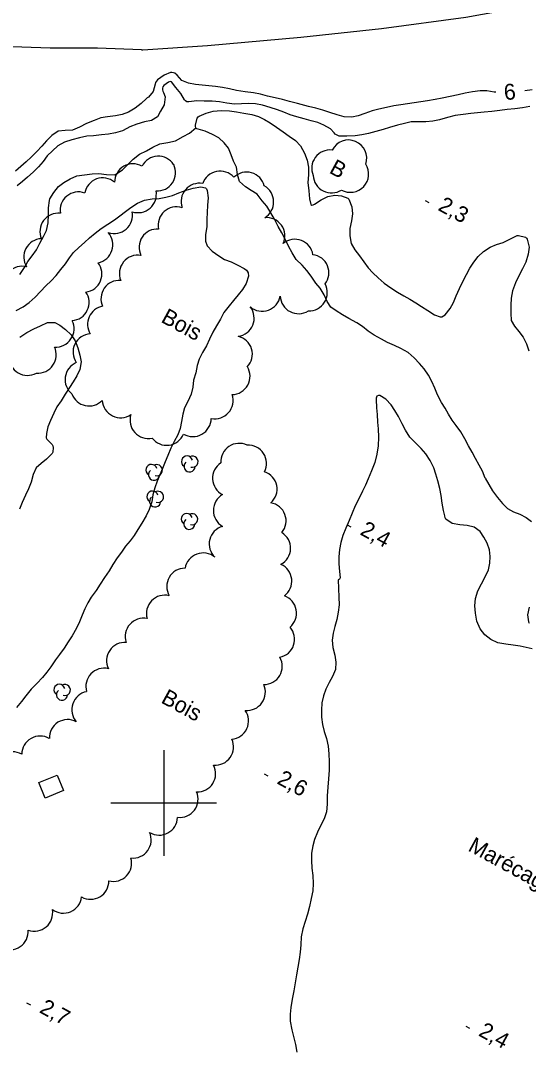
# Model space of a CAD drawing. Extents: x 219136 to 222520, y 5421589 to 5424530.
# Drawn here: x 220572.9 to 220669, y 5422953.1 to 5423147.8 of the extents above; entities that cross this region are included whole.
import ezdxf

# ---------------------------------------------------------------- set-up
doc = ezdxf.new("R2010")
doc.units = 0
for name, color, linetype in [('Level 2', 7, 'Continuous'), ('Level 21', 7, 'Continuous'), ('Level 3', 7, 'Continuous'), ('Level 31', 7, 'Continuous'), ('Level 4', 7, 'Continuous'), ('Level 44', 7, 'Continuous'), ('Level 61', 7, 'Continuous'), ('Level 7', 7, 'Continuous')]:
    doc.layers.add(name, color=color, linetype=linetype)

msp = doc.modelspace()

# ---------------------------------------------------------------- linework, layer by layer
at = {"layer": 'Level 2'}
for points in [[(220630.06, 5423130.89), (220628.77, 5423131.28), (220627.39, 5423131.58), (220625.32, 5423132.19), (220623.8, 5423132.58), (220622.44, 5423132.91), (220621.05, 5423133.24), (220619.65, 5423133.56), (220618.28, 5423133.91), (220616.99, 5423134.19), (220615.4, 5423134.37), (220613.76, 5423134.62), (220612.47, 5423134.97), (220611.11, 5423135.22), (220609.8, 5423135.36), (220608.53, 5423135.49), (220607.27, 5423135.64), (220606.01, 5423135.76), (220604.7, 5423136.01), (220603.44, 5423136.49), (220602.54, 5423137.54), (220602.1, 5423137.92), (220601.85, 5423138), (220601.54, 5423138.03), (220601.26, 5423138.01), (220600.08, 5423137.53), (220598.84, 5423136.64), (220598.46, 5423136.12), (220598.36, 5423135.82), (220598, 5423134.44), (220597.09, 5423133.35), (220596.84, 5423133.22), (220596.72, 5423133.13)], [(220604.13, 5423132.65), (220603.95, 5423132.87), (220603.23, 5423134.09), (220602.32, 5423135.21), (220601.46, 5423136.24), (220601.2, 5423136.33), (220600.93, 5423136.22), (220599.99, 5423135.57), (220599.85, 5423135.34), (220599.78, 5423135.07), (220599.77, 5423134.78), (220599.83, 5423134.51), (220599.97, 5423134.23), (220600.29, 5423133.41), (220600.06, 5423131.91), (220599.42, 5423130.72), (220598.84, 5423129.66), (220597.69, 5423128.97), (220596.36, 5423128.68), (220594.9, 5423128.25), (220593.56, 5423127.75), (220592.36, 5423127.09), (220592.22, 5423127.02)], [(220662.81, 5423134.33), (220662.47, 5423134.34), (220661.13, 5423134.54), (220659.83, 5423134.59), (220658.39, 5423134.4), (220656.99, 5423134.11), (220655.67, 5423133.81), (220654.15, 5423133.47), (220652.66, 5423133.16), (220651.31, 5423132.9), (220649.89, 5423132.69), (220648.65, 5423132.5), (220647.39, 5423132.31), (220646.1, 5423132.12), (220644.81, 5423131.94), (220643.53, 5423131.73), (220642.11, 5423131.43), (220640.67, 5423131.12), (220639.44, 5423130.81), (220638.04, 5423130.31), (220636.8, 5423129.86), (220635.55, 5423129.58), (220634.12, 5423129.66), (220632.81, 5423130.03), (220631.43, 5423130.5), (220630.06, 5423130.89)], [(220669.65, 5423134.78), (220668.32, 5423134.57)], [(220596.72, 5423133.13), (220595.75, 5423132.16), (220594.63, 5423131.31), (220593.34, 5423130.55), (220592.13, 5423130.08), (220590.86, 5423129.87), (220589.38, 5423129.68), (220588.08, 5423129.46), (220586.85, 5423128.97), (220585.41, 5423128.39), (220584.09, 5423127.7), (220582.72, 5423127.15), (220581.35, 5423127.07), (220580.01, 5423126.92), (220578.87, 5423126.12), (220577.86, 5423125.11), (220576.92, 5423124.13), (220575.99, 5423123.11), (220574.93, 5423122.05), (220573.96, 5423121.13), (220572.97, 5423120.28), (220571.98, 5423119.38)], [(220669.25, 5423131.59), (220667.88, 5423131.37), (220666.42, 5423131.14), (220664.96, 5423131.02), (220663.55, 5423130.87), (220662.02, 5423130.66), (220660.62, 5423130.54), (220659.36, 5423130.43), (220658.05, 5423130.27), (220656.61, 5423130.08), (220655.14, 5423129.9), (220653.67, 5423129.51), (220652.16, 5423129.1), (220650.9, 5423128.81), (220649.56, 5423128.69), (220648.22, 5423128.71), (220646.77, 5423128.7), (220645.53, 5423128.41), (220644.19, 5423128.05), (220642.71, 5423127.63), (220641.52, 5423127.24), (220640.1, 5423126.87), (220638.73, 5423126.51), (220637.47, 5423126.23), (220636.22, 5423126.09), (220634.64, 5423125.98), (220633.17, 5423126.02), (220632.4, 5423126.39), (220632.23, 5423126.6), (220631.56, 5423127.39), (220630.3, 5423128.09), (220629.13, 5423128.59), (220627.89, 5423128.93), (220626.59, 5423129.25), (220625.17, 5423129.64), (220623.94, 5423130.05), (220622.7, 5423130.53), (220621.5, 5423130.99), (220620.16, 5423131.43), (220618.65, 5423131.83), (220617.37, 5423132.09), (220616.1, 5423132.18), (220614.72, 5423132.11), (220613.36, 5423132.06), (220611.96, 5423132.26), (220610.55, 5423132.52), (220609.17, 5423132.6), (220607.64, 5423132.61), (220606.24, 5423132.65), (220604.73, 5423132.47), (220604.37, 5423132.51), (220604.13, 5423132.65)], [(220592.22, 5423127.02), (220590.88, 5423126.63), (220589.53, 5423126.37), (220588.22, 5423126.24), (220586.74, 5423126.09), (220585.48, 5423125.97), (220584.08, 5423125.69), (220582.6, 5423125.32), (220581.21, 5423124.85), (220580, 5423124.2), (220578.96, 5423123.26), (220577.97, 5423122.27), (220577.22, 5423121.24), (220576.34, 5423120.22), (220575.29, 5423119.18), (220574.25, 5423118.23), (220573.28, 5423117.41), (220572.26, 5423116.61)], [(220575.72, 5423095.58), (220576.67, 5423096.63), (220577.71, 5423097.73), (220578.71, 5423098.67), (220579.66, 5423099.66), (220580.57, 5423100.78), (220581.42, 5423101.9), (220582.18, 5423103), (220582.96, 5423103.99), (220583.94, 5423104.98), (220585, 5423105.89), (220585.99, 5423106.78), (220587.01, 5423107.68), (220588.15, 5423108.53), (220589.43, 5423109.38), (220590.69, 5423110.16), (220591.7, 5423110.95), (220592.75, 5423111.75), (220593.78, 5423112.54), (220595.02, 5423113.34), (220596.35, 5423113.91), (220597.83, 5423114.15), (220599.15, 5423114.24), (220600.41, 5423114.45), (220601.67, 5423114.8), (220602.85, 5423115.3), (220604.23, 5423115.82), (220605.56, 5423116.19), (220607.03, 5423116.42), (220607.87, 5423116.24), (220608.07, 5423116.03), (220608.21, 5423115.75), (220608.39, 5423114.36), (220608.29, 5423112.98), (220608.24, 5423111.59), (220608.18, 5423110.33), (220608.13, 5423108.87), (220607.93, 5423107.43), (220607.88, 5423106.16), (220608.2, 5423105.25), (220609.18, 5423104.28), (220610.42, 5423103.4), (220611.5, 5423102.72), (220612.75, 5423102.23), (220614.01, 5423101.63), (220615.22, 5423101.02), (220615.66, 5423100.7), (220615.81, 5423100.48), (220615.94, 5423100.2), (220616.04, 5423099.56), (220615.61, 5423098.15), (220614.87, 5423097.03), (220614.06, 5423096), (220613.19, 5423094.95), (220612.39, 5423093.91), (220611.39, 5423092.66), (220610.72, 5423091.45), (220609.95, 5423090.19), (220609.28, 5423088.96), (220608.68, 5423087.63), (220608.1, 5423086.41), (220607.36, 5423085.1), (220606.73, 5423083.88), (220606.35, 5423082.66), (220606.05, 5423081.26)], [(220572.11, 5423093.03), (220573.41, 5423093.75), (220574.58, 5423094.56), (220575.72, 5423095.58)], [(220572.76, 5423088.04), (220574.09, 5423088.88), (220575.43, 5423089.6), (220576.68, 5423090.19), (220578.02, 5423090.77), (220579.41, 5423090.77), (220580.38, 5423090.29), (220581.43, 5423089.47), (220582.48, 5423088.49), (220583.27, 5423087.3), (220583.73, 5423086.03), (220584.11, 5423084.59), (220584.39, 5423083.34), (220584.12, 5423081.92), (220583.55, 5423080.73), (220582.87, 5423079.58), (220582.15, 5423078.53), (220581.38, 5423077.27), (220580.6, 5423075.99), (220579.81, 5423074.83), (220579.23, 5423073.63), (220578.6, 5423072.29), (220578.11, 5423071.08), (220577.82, 5423069.81), (220577.75, 5423069), (220577.89, 5423068.77), (220578.89, 5423067.76), (220579.01, 5423067.49), (220579.07, 5423067.2), (220579.04, 5423066.29), (220578.91, 5423066.02), (220577.85, 5423064.99), (220576.81, 5423064.15), (220575.87, 5423063.3), (220575.3, 5423062.09), (220574.94, 5423060.64), (220574.41, 5423059.39), (220573.84, 5423058.18), (220573.26, 5423056.79), (220572.73, 5423055.52)], [(220606.05, 5423081.26), (220605.64, 5423079.91), (220605.51, 5423078.58), (220605.21, 5423077.23), (220604.55, 5423075.87), (220603.96, 5423074.67), (220603.61, 5423073.47), (220603.36, 5423072.06), (220603.11, 5423070.76), (220602.68, 5423069.55), (220601.95, 5423068.32), (220601.36, 5423067.02), (220600.8, 5423065.66), (220600.27, 5423064.45), (220599.77, 5423063.23), (220599.26, 5423062.03), (220598.74, 5423060.79), (220598.29, 5423059.57), (220597.95, 5423058.21), (220597.77, 5423056.93), (220597.26, 5423055.44), (220596.65, 5423054.23), (220595.86, 5423052.87), (220595.11, 5423051.68), (220594.38, 5423050.57), (220593.63, 5423049.54), (220592.8, 5423048.5), (220592.04, 5423047.42), (220591.17, 5423046.29), (220590.38, 5423045.04), (220589.71, 5423043.89), (220588.82, 5423042.59), (220588, 5423041.34), (220587.2, 5423040.13), (220586.3, 5423038.91), (220585.65, 5423037.81), (220585.08, 5423036.66), (220584.6, 5423035.46), (220584.08, 5423034.21), (220583.53, 5423033.03), (220582.7, 5423031.58), (220581.93, 5423030.43), (220581.15, 5423029.24), (220580.3, 5423028.05), (220579.53, 5423027.02), (220578.66, 5423025.72), (220577.92, 5423024.7), (220577.07, 5423023.71), (220575.99, 5423022.59), (220574.95, 5423021.5), (220573.94, 5423020.26), (220573.09, 5423019.2), (220572.13, 5423018.05)]]:
    msp.add_lwpolyline(points, dxfattribs=at)
at = {"layer": 'Level 21'}
for points in [[(220595.78, 5423142.32), (220596.07, 5423142.34), (220608.3, 5423143.12), (220625.95, 5423144.72), (220641.18, 5423146.34), (220657.15, 5423148.52), (220677.44, 5423152.18)], [(220595.78, 5423142.32), (220587.48, 5423142.64), (220578.53, 5423142.66), (220562.37, 5423143.22), (220541.52, 5423144.77), (220523.65, 5423145.87), (220511.93, 5423146.79), (220506.04, 5423146.14), (220502.22, 5423144.49), (220498.38, 5423141.58), (220495.91, 5423137.1), (220483.71, 5423103.12), (220471.88, 5423067.02), (220455.93, 5423018.9), (220442.13, 5422979.2), (220434.81, 5422959.19)]]:
    msp.add_lwpolyline(points, dxfattribs=at)
at = {"layer": 'Level 3'}
for p, q in [((220649.45, 5423113.85), (220650.15, 5423113.47)), ((220634.71, 5423052.55), (220635.41, 5423052.17)), ((220619.01, 5423005.49), (220619.71, 5423005.11)), ((220574.08, 5422962.23), (220574.78, 5422961.85)), ((220657.12, 5422957.85), (220657.82, 5422957.47))]:
    msp.add_line(p, q, dxfattribs=at)
at = {"layer": 'Level 31'}
msp.add_lwpolyline([(220579.88, 5423005.25), (220581.06, 5423002.34), (220577.56, 5423000.93), (220576.39, 5423003.84)], close=True, dxfattribs=at)
at = {"layer": 'Level 4'}
for points in [[(220606.08, 5423127.57), (220606, 5423127.82), (220606.01, 5423128.08), (220606.3, 5423129.41), (220606.49, 5423129.63), (220606.71, 5423129.76), (220608.05, 5423130.33), (220609.37, 5423130.75), (220610.89, 5423130.85), (220612.44, 5423130.77), (220613.76, 5423130.59), (220615.15, 5423130.35), (220616.64, 5423130.09), (220617.9, 5423129.7), (220619.03, 5423129.13), (220620.15, 5423128.54), (220621.33, 5423127.73), (220622.59, 5423126.82), (220623.74, 5423125.98), (220624.9, 5423125.16), (220625.87, 5423124.18), (220626.64, 5423122.76), (220627.15, 5423121.49), (220627.4, 5423120.15), (220627.4, 5423118.72), (220627.26, 5423117.27), (220627.45, 5423115.69), (220627.58, 5423114.19), (220627.8, 5423113.11), (220628.03, 5423112.96), (220628.29, 5423113), (220628.54, 5423113.14), (220629.76, 5423113.94), (220631.01, 5423114.59), (220632.33, 5423114.84), (220633.62, 5423114.75), (220634.8, 5423114.27), (220635, 5423114.07), (220635.57, 5423112.65), (220635.71, 5423111.31), (220635.48, 5423110), (220635.19, 5423108.58), (220635.18, 5423107.15), (220635.46, 5423105.74), (220636.15, 5423104.52), (220637, 5423103.41), (220637.87, 5423102.24), (220638.65, 5423101.12), (220639.52, 5423100.2), (220640.58, 5423099.26), (220641.72, 5423098.25), (220642.94, 5423097.31), (220644.18, 5423096.53), (220645.4, 5423095.82), (220646.57, 5423095.21), (220647.68, 5423094.52), (220648.75, 5423093.81), (220649.94, 5423093.03), (220651.21, 5423092.21), (220652.28, 5423091.84), (220652.62, 5423091.87), (220652.94, 5423092.03), (220653.24, 5423092.23), (220654.15, 5423093.41)], [(220572.81, 5423099.84), (220573.66, 5423101.19), (220574.33, 5423102.34), (220575.1, 5423103.41), (220575.93, 5423104.53), (220576.59, 5423105.78), (220577.28, 5423107.03), (220577.82, 5423108.18), (220578.12, 5423109.64), (220578.2, 5423111.2), (220578.24, 5423112.49), (220578.38, 5423113.87), (220578.49, 5423114.13), (220579.2, 5423115.34), (220580.11, 5423116.49), (220581.1, 5423117.27), (220582.33, 5423117.96), (220583.57, 5423118.52), (220585.03, 5423118.72), (220586.49, 5423118.89), (220587.75, 5423118.97), (220589.17, 5423118.75), (220590.69, 5423118.71), (220590.94, 5423118.81), (220592.19, 5423119.65), (220593.25, 5423120.7), (220594.23, 5423121.68), (220595.44, 5423122.59), (220596.72, 5423123.25), (220597.95, 5423123.91), (220599.25, 5423124.55), (220600.78, 5423124.81), (220602.22, 5423125.13), (220603.68, 5423125.91), (220604.86, 5423126.56), (220606.06, 5423127.55), (220606.08, 5423127.57)], [(220660.82, 5423061.37), (220660.29, 5423062.68), (220659.68, 5423063.82), (220658.99, 5423065.06), (220658.32, 5423066.28), (220657.65, 5423067.51), (220656.94, 5423068.81), (220656.18, 5423070.14), (220655.32, 5423071.32), (220654.52, 5423072.35), (220653.84, 5423073.45), (220653.21, 5423074.59), (220652.52, 5423075.68), (220651.78, 5423077.12), (220651.24, 5423078.39), (220650.69, 5423079.61), (220650.09, 5423080.82), (220649.25, 5423082.05), (220648.38, 5423083.07), (220647.35, 5423084.13), (220646.22, 5423085.13), (220644.86, 5423085.9), (220643.62, 5423086.47), (220642.33, 5423087.03), (220641.16, 5423087.62), (220639.82, 5423088.38), (220638.67, 5423089.18), (220637.6, 5423090.01), (220636.54, 5423090.75), (220635, 5423091.52), (220633.82, 5423092.26), (220632.62, 5423092.97), (220631.6, 5423093.69), (220630.93, 5423094.78), (220630.32, 5423096.01), (220629.56, 5423097.26), (220628.77, 5423098.25), (220627.91, 5423099.52), (220627.08, 5423100.64), (220626.2, 5423101.61), (220625.06, 5423102.69), (220624.27, 5423103.97), (220623.57, 5423105.23), (220622.98, 5423106.53), (220622.35, 5423107.74), (220621.67, 5423108.96), (220620.94, 5423110.29), (220620.27, 5423111.53), (220619.51, 5423112.77), (220618.64, 5423113.81), (220617.7, 5423115.03), (220616.51, 5423115.75), (220615.44, 5423116.43), (220614.36, 5423117.45), (220613.97, 5423118.77), (220613.79, 5423120.14), (220613.22, 5423121.28), (220612.75, 5423122.5), (220612.23, 5423123.75), (220611.44, 5423124.76), (220610.41, 5423125.71), (220609.23, 5423126.32), (220607.85, 5423126.93), (220606.51, 5423127.3), (220606.26, 5423127.38), (220606.08, 5423127.57)], [(220654.15, 5423093.41), (220654.77, 5423094.6), (220655.33, 5423095.82), (220655.93, 5423097.23), (220656.58, 5423098.55), (220657.28, 5423099.87), (220657.9, 5423101.04), (220658.64, 5423102.2), (220659.44, 5423103.24), (220660.47, 5423104.19), (220661.74, 5423105), (220662.92, 5423105.53), (220664.22, 5423105.93), (220665.59, 5423106.62), (220666.83, 5423107.2), (220667.09, 5423107.23), (220668.4, 5423106.92), (220668.6, 5423106.74), (220668.76, 5423106.52), (220669.1, 5423105.03), (220668.91, 5423103.68), (220668.48, 5423102.22), (220667.88, 5423100.95), (220667.17, 5423099.59), (220666.55, 5423098.28), (220665.98, 5423096.78), (220665.71, 5423095.39), (220665.64, 5423094.06), (220665.63, 5423092.57), (220665.68, 5423091.19), (220666.31, 5423090.07), (220667.14, 5423089.07), (220667.97, 5423088.03), (220668.62, 5423086.73), (220669.06, 5423085.42)], [(220660.82, 5423061.37), (220661.48, 5423060.15), (220662.19, 5423058.96), (220663.12, 5423057.71), (220664.07, 5423056.56), (220665, 5423055.62), (220666.16, 5423055.03), (220667.33, 5423054.58), (220668.53, 5423053.97), (220669.52, 5423053.19)], [(220669.11, 5423036.97), (220668.8, 5423035.58), (220668.96, 5423034.25), (220669.11, 5423034)]]:
    msp.add_lwpolyline(points, dxfattribs=at)
at = {"layer": 'Level 44'}
for centre, radius, start, end in [((220634.94, 5423121.82), 3.46, 341.2343, 153.3156), ((220598.98, 5423118.76), 3.46, 33.0955, 153.0955), ((220631.45, 5423119.93), 3.46, 83.4428, 203.4428), ((220594.17, 5423117.32), 3.46, 60.2405, 180.2405), ((220598.78, 5423119.12), 3.46, 266.2105, 26.2105), ((220635.3, 5423118.85), 3.46, 240.9083, 32.4224), ((220610.66, 5423115.94), 3.46, 41.4724, 161.4724), ((220615.67, 5423115.75), 3.46, 14.144, 134.144), ((220631.73, 5423118.73), 3.46, 182.8831, 302.8831), ((220588.48, 5423114.66), 3.46, 49.9559, 169.9559), ((220606.74, 5423113.64), 3.46, 79.4076, 199.4076), ((220617.33, 5423113.57), 3.46, 300.6712, 60.6712), ((220583.86, 5423112.01), 3.46, 69.6501, 189.6501), ((220595.15, 5423115), 3.46, 251.1076, 11.1076), ((220602.41, 5423109.19), 3.46, 72.2036, 192.2036), ((220580.05, 5423107.99), 3.46, 83.3527, 203.3527), ((220590.63, 5423111.05), 3.46, 251.2184, 11.2184), ((220619.45, 5423107.15), 3.46, 335.8189, 95.8189), ((220598.8, 5423105), 3.46, 86.2663, 206.2663), ((220576.99, 5423103.16), 3.46, 92.0842, 212.0842), ((220586.92, 5423105.48), 3.46, 281.4805, 41.4805), ((220624.8, 5423103.05), 3.46, 9.1996, 129.1996), ((220595.08, 5423100.05), 3.46, 79.8264, 202.2086), ((220627.78, 5423100.16), 3.46, 322.8075, 82.8075), ((220573.19, 5423097.96), 3.46, 75.4336, 195.4336), ((220584.85, 5423099.98), 3.46, 277.2419, 37.2419), ((220591.59, 5423095.29), 3.46, 85.3745, 204.5692), ((220627.48, 5423096.45), 3.46, 267.893, 27.893), ((220582.43, 5423094.59), 3.46, 274.4586, 34.4586), ((220618.62, 5423096.37), 3.46, 229.7295, 349.7295), ((220625.49, 5423095.91), 3.46, 182.4908, 302.4908), ((220589.07, 5423090.45), 3.46, 100.4763, 211.2915), ((220613.64, 5423091.61), 3.46, 277.754, 37.754), ((220579.59, 5423089.61), 3.46, 266.0826, 26.0826), ((220586.3, 5423085.19), 3.46, 93.1462, 214.9454), ((220613.3, 5423084.81), 3.46, 316.5367, 76.5367), ((220576.21, 5423084.69), 3.46, 265.0537, 25.0537), ((220574.2, 5423084.25), 3.46, 179.6383, 299.6383), ((220584.8, 5423080.01), 3.46, 112.6435, 231.5933), ((220612.86, 5423080.63), 3.46, 271.2836, 31.2836), ((220585.9, 5423078.48), 3.46, 199.9924, 315.7195), ((220591.84, 5423076.25), 3.46, 183.2022, 304.2297), ((220609.66, 5423076.04), 3.46, 258.8516, 18.8516), ((220597.08, 5423072.32), 3.46, 162.0456, 282.0456), ((220605.52, 5423072.69), 3.46, 239.2993, 359.2993), ((220600.56, 5423071.04), 3.46, 217.4604, 337.4604), ((220614.27, 5423064.5), 3.46, 63.9694, 183.9694), ((220615.99, 5423064.15), 3.46, 333.3057, 93.3057), ((220597.67, 5423062.93), 1.05, 14.9746, 237.6589), ((220598.71, 5423062.89), 1.05, 252.1531, 117.8417), ((220604.4, 5423064.52), 1.05, 14.9746, 237.6589), ((220604.89, 5423063.6), 1.05, 130.3069, 357.764), ((220605.44, 5423064.48), 1.05, 252.1531, 117.8417), ((220612.7, 5423061.35), 3.46, 122.9851, 242.9851), ((220598.16, 5423062.01), 1.05, 130.3069, 357.764), ((220617.97, 5423059.31), 3.46, 311.2801, 71.2801), ((220597.88, 5423057.89), 1.05, 14.9746, 237.6589), ((220598.92, 5423057.85), 1.05, 252.1531, 117.8417), ((220612.85, 5423055.26), 3.46, 119.7381, 239.7381), ((220598.37, 5423056.97), 1.05, 130.3069, 357.764), ((220619.68, 5423053.3), 3.46, 320.3761, 80.3761), ((220604.34, 5423053.66), 1.05, 14.9746, 237.6589), ((220605.38, 5423053.62), 1.05, 252.1531, 117.8417), ((220604.83, 5423052.74), 1.05, 130.3069, 357.764), ((220612.06, 5423048.94), 3.46, 106.1241, 226.1241), ((220620.53, 5423048.14), 3.46, 298.2392, 58.2392), ((220607.45, 5423043.78), 3.46, 50.2613, 170.2613), ((220604.03, 5423040.9), 3.46, 89.9382, 209.9383), ((220620.77, 5423041.92), 3.46, 306.289, 66.289), ((220600.19, 5423035.81), 3.46, 75.9411, 195.9411), ((220621.65, 5423035.87), 3.46, 310.2325, 70.2325), ((220596.18, 5423031.46), 3.46, 78.7101, 198.7101), ((220621.29, 5423030.93), 3.46, 281.4044, 41.4044), ((220592.66, 5423026.89), 3.46, 86.029, 206.029), ((220618.96, 5423025.83), 3.46, 269.392, 29.392), ((220588.73, 5423022.01), 3.46, 76.3599, 196.3599), ((220580.26, 5423021.38), 1.05, 14.9746, 237.6589), ((220580.75, 5423020.46), 1.05, 130.3069, 357.764), ((220581.3, 5423021.34), 1.05, 252.1531, 117.8417), ((220586.07, 5423017.63), 3.46, 101.1005, 221.1005), ((220615.76, 5423020.94), 3.46, 264.3772, 24.3772), ((220612.59, 5423015.51), 3.46, 274.9963, 34.9963), ((220581.83, 5423012.3), 3.46, 61.9645, 181.9645), ((220576.62, 5423009.19), 3.46, 59.7078, 179.7078), ((220609.75, 5423010.6), 3.46, 264.8435, 24.8435), ((220571.43, 5423006.2), 3.46, 60.0729, 180.0729), ((220606.36, 5423005.54), 3.46, 267.6075, 27.6075), ((220603.04, 5423000.72), 3.46, 263.2187, 23.2187), ((220599.16, 5422997.38), 3.46, 238.2294, 358.2294), ((220594.17, 5422993.04), 3.46, 263.9021, 23.9021), ((220590.47, 5422988.64), 3.46, 255.9201, 15.9201), ((220586.17, 5422985.25), 3.46, 240.5069, 0.5069), ((220581.02, 5422982.63), 3.46, 233.4613, 353.4613), ((220575.55, 5422979.23), 3.46, 250.3267, 10.3267), ((220570.93, 5422975.73), 3.46, 243.7922, 3.7922)]:
    msp.add_arc(centre, radius, start, end, dxfattribs=at)
at = {"layer": 'Level 61'}
for points in [[(220600, 5423010), (220600, 5423000), (220600, 5422990)], [(220590, 5423000), (220600, 5423000), (220610, 5423000)]]:
    msp.add_lwpolyline(points, dxfattribs=at)
at = {"layer": 'Level 7'}
for points in [[(220653.15, 5423054.24), (220652.88, 5423055.24), (220652.68, 5423056.67), (220652.44, 5423058.09), (220652.19, 5423059.4), (220651.84, 5423060.87), (220651.48, 5423062.11), (220651.06, 5423063.35), (220650.37, 5423064.73), (220649.56, 5423065.97), (220648.71, 5423066.99), (220647.59, 5423068.08), (220646.52, 5423069.12), (220645.75, 5423070.43), (220645.11, 5423071.62), (220644.37, 5423073.01), (220643.73, 5423074.18), (220643.02, 5423075.24), (220642.02, 5423076.31), (220640.87, 5423076.99), (220640.6, 5423077.01), (220640.32, 5423076.84), (220640.17, 5423076.49), (220640.15, 5423076.23), (220640.23, 5423074.66), (220640.34, 5423073.42), (220640.45, 5423071.98), (220640.56, 5423070.71), (220640.59, 5423069.1), (220640.55, 5423067.46), (220640.33, 5423065.9), (220639.91, 5423064.32), (220639.32, 5423062.77), (220638.68, 5423061.25), (220638.15, 5423060.06), (220637.61, 5423058.93), (220636.91, 5423057.5), (220636.22, 5423056.12), (220635.62, 5423054.76), (220635.06, 5423053.37), (220634.46, 5423051.92), (220633.89, 5423050.53), (220633.52, 5423049.19), (220633.25, 5423047.87), (220633.12, 5423046.52), (220633.13, 5423045.2), (220633.22, 5423043.71), (220633.39, 5423042.53), (220633.22, 5423042.32), (220632.99, 5423042.14), (220633.14, 5423038.87)], [(220669.68, 5423029.1), (220667.42, 5423029.64), (220666.07, 5423029.8), (220664.71, 5423030), (220663.18, 5423030.28), (220661.89, 5423030.88), (220660.75, 5423031.78), (220659.86, 5423032.91), (220659.24, 5423034.35), (220658.99, 5423035.86), (220658.86, 5423037.28), (220658.94, 5423038.64), (220659.39, 5423040.06), (220660.08, 5423041.4), (220660.8, 5423042.74), (220661.39, 5423044.04), (220661.68, 5423045.3), (220661.74, 5423046.57), (220661.59, 5423047.85), (220661.15, 5423049.1), (220660.55, 5423050.21), (220659.84, 5423051.32), (220658.7, 5423052.1), (220657.4, 5423052.42), (220655.99, 5423052.57), (220654.53, 5423052.81), (220653.38, 5423053.65), (220653.25, 5423053.9), (220653.15, 5423054.24), (220653.15, 5423054.24)], [(220633.14, 5423038.87), (220633.16, 5423037.41), (220633.01, 5423036.07), (220632.72, 5423034.68), (220632.38, 5423033.35), (220632.06, 5423032.11), (220631.84, 5423030.75), (220632, 5423029.38), (220632.38, 5423027.95), (220632.55, 5423026.58), (220632.46, 5423025.22), (220631.89, 5423023.91), (220631.26, 5423022.74), (220630.67, 5423021.51), (220630.19, 5423020.23), (220629.93, 5423018.92), (220629.82, 5423017.55), (220629.83, 5423016.2), (220630.01, 5423014.84), (220630.36, 5423013.5), (220630.78, 5423012.16), (220631.12, 5423010.73), (220631.25, 5423009.29), (220631.3, 5423007.76), (220631.28, 5423006.2), (220631.19, 5423004.58), (220631.04, 5423002.98), (220630.93, 5423001.35), (220630.9, 5422999.75), (220630.78, 5422998.34), (220630.33, 5422996.98), (220629.66, 5422995.65), (220629.09, 5422994.49), (220628.54, 5422993.11), (220628.18, 5422991.9), (220627.94, 5422990.52), (220627.96, 5422989.14), (220628.04, 5422987.7), (220628.17, 5422986.26), (220628.28, 5422984.79), (220628.21, 5422983.38), (220627.91, 5422981.94), (220627.58, 5422980.42), (220627.2, 5422978.98), (220626.75, 5422977.59), (220626.3, 5422976.2), (220625.98, 5422974.71), (220625.9, 5422973.22), (220625.83, 5422971.8), (220625.61, 5422970.43), (220625.36, 5422969), (220625.13, 5422967.53), (220624.85, 5422966.01), (220624.61, 5422964.49), (220624.3, 5422962.94), (220624.03, 5422961.32), (220623.92, 5422960.06), (220623.94, 5422958.79), (220624.23, 5422957.14), (220624.53, 5422955.85), (220624.9, 5422954.35), (220625.15, 5422952.9)]]:
    msp.add_lwpolyline(points, dxfattribs=at)

# ---------------------------------------------------------------- texts
at = {"layer": 'Level 2'}
msp.add_text('6', height=3, rotation=5.0982, dxfattribs=at).set_placement((220664.46, 5423132.8))
at = {"layer": 'Level 3'}
for s, p in [('2,3', (220651.69, 5423112.11)), ('2,4', (220636.95, 5423050.81)), ('2,6', (220621.24, 5423003.75)), ('2,7', (220576.32, 5422960.49)), ('2,4', (220659.36, 5422956.11))]:
    msp.add_text(s, height=3, rotation=331.383, dxfattribs=at).set_placement(p)
at = {"layer": 'Level 44'}
for s, p in [('B', (220631.12, 5423119.16)), ('Bois', (220599.31, 5423090.97)), ('Bois', (220599.31, 5423019.04))]:
    msp.add_text(s, height=3, rotation=331.3547, dxfattribs=at).set_placement(p)
at = {"layer": 'Level 7'}
msp.add_text('Marécage', height=3, rotation=331.383, dxfattribs=at).set_placement((220657.36, 5422991.07))

doc.saveas('drawing.dxf')
